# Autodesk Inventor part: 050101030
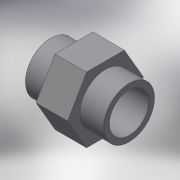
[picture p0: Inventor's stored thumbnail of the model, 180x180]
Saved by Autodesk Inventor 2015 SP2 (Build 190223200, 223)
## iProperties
Created: 2017-10
Part Number: 050101030
Material: Generic
Description: PLASSON THREADED SOCKET PVC 3"
Document SubType Name: Modeling
Designer: KIM
Density: 1 g/cm^3
Appearance: Default
Author: KIM
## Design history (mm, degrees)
derived "050101.ipt"
feature "Solid1::050101.ipt"
tag "TaggingFeature1"
body "Solid1"
other parameters: "d0" = 89, "d1" = 84.926, "d2" = 108, "d3" = 84.926, "d4" = 76.4334, "d5" = 33, "d6" = 33, "d7" = 101.9112, "d8" = 101.9112, "d10" = 23.1, "d13" = 0, "d14" = 0.84926, "d15" = 24, "G_" = 84.926, "C_" = 108, "B_" = 24, "lt_" = 33, "H_" = 89
